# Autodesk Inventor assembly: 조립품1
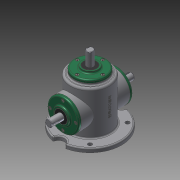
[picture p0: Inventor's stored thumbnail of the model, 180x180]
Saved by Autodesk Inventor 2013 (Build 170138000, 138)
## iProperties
Created: 2018-04
Part Number: 조립품1
Document SubType Name: Assembly
Designer: Administrator
Author: Administrator
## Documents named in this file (16)
- C:\Users\Administrator\Desktop\새 폴더\480408V1011\조립품1.iam
- C:\Users\Administrator\Desktop\새 폴더\480408V1011\본체.ipt
- C:\Users\Administrator\Desktop\새 폴더\480408V1011\메인 베벨기어.ipt
- C:\Users\Administrator\Desktop\새 폴더\480408V1011\메인 축.ipt
- 메인 축.ipt
- C:\Users\Administrator\Desktop\새 폴더\480408V1011\서브 베벨기어.ipt
- C:\Users\Administrator\Desktop\새 폴더\480408V1011\서브 축.ipt
- 서브 축.ipt
- C:\Users\Administrator\Desktop\새 폴더\480408V1011\커버.ipt
- C:\Users\Administrator\Desktop\새 폴더\480408V1011\키 4x4.ipt
- C:\Users\Administrator\Desktop\새 폴더\480408V1011\키 5x5.ipt
- C:\Users\Administrator\Desktop\새 폴더\480408V1011\오일 실.ipt
- 오일 실.ipt
- C:\Users\Administrator\Desktop\새 폴더\480408V1011\베어링 6203.ipt
- C:\Users\Administrator\Desktop\새 폴더\480408V1011\볼트 M4.ipt
- 볼트 M4.ipt
